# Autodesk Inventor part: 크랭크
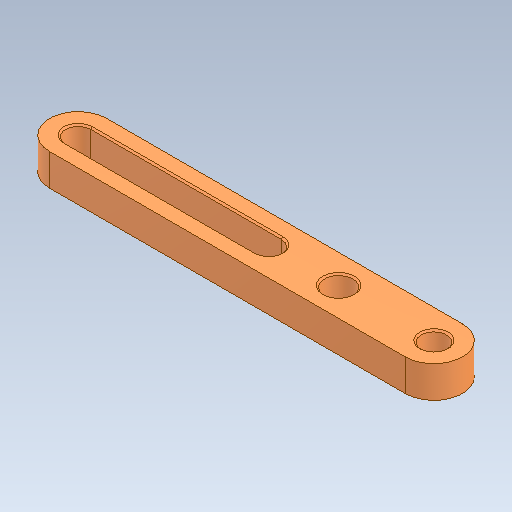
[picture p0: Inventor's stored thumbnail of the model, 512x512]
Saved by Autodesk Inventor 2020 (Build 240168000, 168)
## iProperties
Created: 2024-04
Part Number: 크랭크
Material: 알루미늄 6061
Document SubType Name: Modeling
Designer: oem
Density: 2.71 g/cm^3
Appearance: 기본값
Mass: 43.9367 g
Surface Area: 79.2918 cm^2
Volume: 16.2128 cm^3
Sending System: Autodesk Inventor 2025
Preprocessor: ST-DEVELOPER v20
Author: jhkim
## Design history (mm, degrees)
feature "솔리드1"
node "솔리드2"
